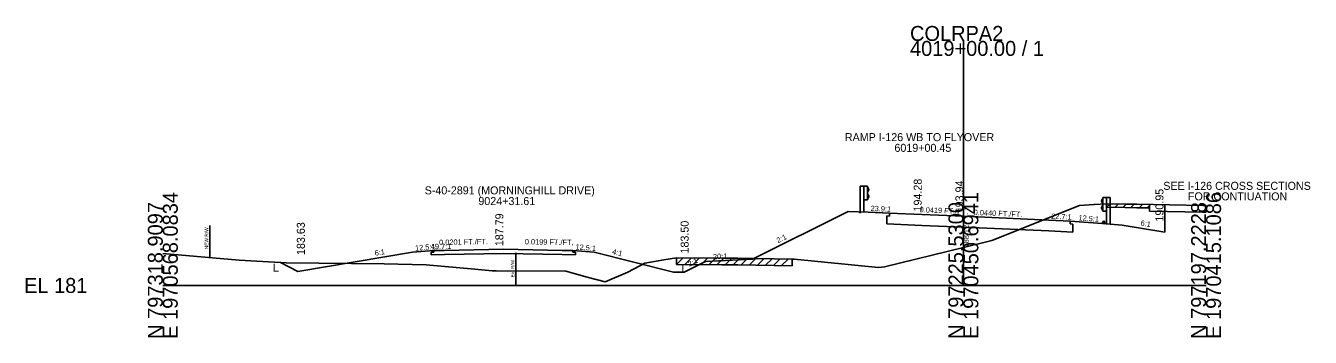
# Model space of a CAD drawing. Extents: x -26 to 1971083, y -10 to 798159.
# Drawn here: x -25.7 to 215, y 3490.3 to 3548.6 of the extents above; entities that cross this region are included whole.
import ezdxf

# ---------------------------------------------------------------- set-up
doc = ezdxf.new("R2010")
doc.units = 0
for name, color, linetype in [('RD_GPK_XS_Cell', 7, 'Continuous'), ('RD_XS_Base', 7, 'Continuous'), ('RD_XS_CurbTop', 7, 'Continuous'), ('RD_XS_EarthShd', 7, 'Continuous'), ('RD_XS_ExGround', 7, 'Continuous'), ('RD_XS_ExPaveRet', 7, 'Continuous'), ('RD_XS_ExRW', 7, 'Continuous'), ('RD_XS_GR', 7, 'Continuous'), ('RD_XS_Misc_Line', 7, 'Continuous'), ('RD_XS_NewRW', 7, 'Continuous'), ('RD_XS_Pave', 7, 'Continuous'), ('RD_XS_PaveShd', 7, 'Continuous'), ('RD_XS_TieSlope', 7, 'Continuous'), ('RD_XS_TX_Elev_EX', 7, 'Continuous'), ('RD_XS_TX_Elev_PR', 7, 'Continuous'), ('RD_XS_TX_Misc', 7, 'Continuous'), ('RD_XS_TX_MkPT', 7, 'Continuous'), ('RD_XS_TX_Notes', 7, 'Continuous'), ('RD_XS_TX_Profile', 7, 'Continuous'), ('RD_XS_TX_ShdSlope', 7, 'Continuous'), ('RD_XS_TX_Slope', 7, 'Continuous'), ('RD_XS_TX_Station', 7, 'Continuous')]:
    doc.layers.add(name, color=color, linetype=linetype)

msp = doc.modelspace()

# ---------------------------------------------------------------- linework, layer by layer
at = {"layer": 'RD_GPK_XS_Cell'}
for p, q in [((150, 3500), (150, 3545.75)), ((0, 3500), (150, 3500)), ((150, 3500), (195.47, 3500))]:
    msp.add_line(p, q, dxfattribs=at)
at = {"layer": 'RD_XS_Base'}
for p, q in [((135.67, 3513), (136.17, 3512.98)), ((135.67, 3511.52), (135.67, 3513)), ((136.17, 3512.98), (136.17, 3513.54)), ((170, 3511.5), (170, 3512.06)), ((142.19, 3511.24), (135.67, 3511.52)), ((142.19, 3511.24), (150, 3510.9)), ((150, 3510.9), (166, 3510.2)), ((166, 3510.2), (170.5, 3510)), ((170.5, 3511.48), (170, 3511.5)), ((170.5, 3510), (170.5, 3511.48)), ((50.3, 3506.22), (50.8, 3506.23)), ((50.3, 3505.74), (50.3, 3506.22)), ((52.8, 3505.79), (50.3, 3505.74)), ((50.8, 3506.23), (50.8, 3506.53)), ((52.8, 3505.79), (63.8, 3506.01)), ((63.8, 3506.01), (74.8, 3505.79)), ((74.8, 3505.79), (77.3, 3505.74)), ((76.8, 3506.23), (76.8, 3506.53)), ((77.3, 3506.22), (76.8, 3506.23)), ((77.3, 3505.74), (77.3, 3506.22))]:
    msp.add_line(p, q, dxfattribs=at)
at = {"layer": 'RD_XS_CurbTop'}
for p, q in [((176, 3511.58), (176.25, 3512.04)), ((176.47, 3511.55), (176.41, 3511.98)), ((176, 3511.58), (176.47, 3511.55))]:
    msp.add_line(p, q, dxfattribs=at)
msp.add_ellipse((176.32, 3511.96), major_axis=(0, -0.131), ratio=0.686, start_param=1.762783, end_param=4.036677, dxfattribs=at)
at = {"layer": 'RD_XS_EarthShd'}
for p, q in [((136.17, 3513.54), (132.16, 3513.7)), ((170, 3512.06), (176, 3511.58)), ((50.8, 3506.53), (46.8, 3506.21)), ((76.8, 3506.53), (80.81, 3506.21))]:
    msp.add_line(p, q, dxfattribs=at)
at = {"layer": 'RD_XS_ExGround'}
msp.add_lwpolyline([(0, 3506), (14.31, 3504.73), (23.1, 3504.26), (41.47, 3504.04), (49.34, 3503.89), (58.48, 3503.05), (61.68, 3502.76), (62.44, 3502.73), (75.48, 3502.66), (79.51, 3501.55), (82.88, 3500.65), (87.15, 3502.49), (90.31, 3504.15), (93.87, 3504.77), (96.27, 3505.16), (104.74, 3505.12), (107.73, 3505.11), (117.9, 3504.93), (118.28, 3504.89), (122.11, 3504.53), (130.29, 3503.76), (134.12, 3503.39), (135.24, 3503.48), (150, 3507.12), (155.33, 3508.43), (171.76, 3514.98), (174.5, 3515.14), (176.84, 3515.25), (180.28, 3515.2), (182.52, 3515.18), (194.83, 3514.99), (195.47, 3514.98)], dxfattribs=at)
at = {"layer": 'RD_XS_ExPaveRet'}
for p, q in [((176.84, 3514.63), (176.84, 3515.25)), ((176.84, 3514.63), (180.28, 3514.57)), ((180.28, 3514.57), (182.52, 3514.55)), ((182.52, 3514.55), (184.84, 3514.52)), ((184.84, 3515.14), (184.84, 3513.89)), ((195.47, 3514.98), (195.46, 3513.73)), ((96.27, 3503.91), (96.27, 3505.16)), ((117.9, 3504.93), (117.9, 3503.68)), ((96.27, 3503.91), (104.74, 3503.87)), ((104.74, 3503.87), (107.73, 3503.86)), ((107.73, 3503.86), (117.9, 3503.68))]:
    msp.add_line(p, q, dxfattribs=at)
msp.add_lwpolyline([(184.84, 3513.89), (194.81, 3513.74), (195.46, 3513.73)], dxfattribs=at)
at = {"layer": 'RD_XS_ExRW'}
msp.add_line((66.13, 3506.12), (66.13, 3500.12), dxfattribs=at)
at = {"layer": 'RD_XS_GR'}
for p, q in [((131.34, 3518.58), (130.67, 3518.58)), ((130.67, 3518.58), (130.67, 3513.52)), ((132.01, 3518.58), (131.34, 3518.58)), ((131.34, 3518.58), (131.34, 3513.64)), ((132.01, 3516.01), (132.01, 3518.58)), ((132.01, 3518.42), (132.28, 3517.98)), ((132.28, 3517.87), (132.01, 3517.43)), ((132.28, 3516.72), (132.01, 3517.16)), ((132.01, 3516.17), (132.28, 3516.61)), ((132.28, 3517.98), (132.28, 3517.87)), ((132.28, 3516.61), (132.28, 3516.72)), ((132.01, 3516.01), (131.34, 3516.01)), ((176.15, 3516.3), (175.88, 3515.86)), ((175.88, 3515.86), (175.88, 3515.75)), ((175.88, 3515.75), (176.15, 3515.31)), ((175.88, 3514.6), (176.15, 3515.04)), ((175.88, 3514.49), (175.88, 3514.6)), ((176.15, 3514.05), (175.88, 3514.49)), ((176.15, 3516.46), (176.81, 3516.46)), ((176.15, 3513.89), (176.15, 3516.46)), ((176.81, 3516.46), (177.48, 3516.46)), ((176.81, 3516.46), (176.81, 3511.52)), ((177.48, 3516.46), (177.48, 3511.4)), ((176.15, 3513.89), (176.81, 3513.89))]:
    msp.add_line(p, q, dxfattribs=at)
at = {"layer": 'RD_XS_Misc_Line'}
for p, q in [((176.84, 3514.63), (177.46, 3515.24)), ((178.36, 3514.6), (178.98, 3515.22)), ((179.88, 3514.58), (180.5, 3515.2)), ((181.39, 3514.56), (182.02, 3515.18)), ((182.91, 3514.54), (183.53, 3515.16)), ((184.43, 3514.52), (185.05, 3515.14)), ((96.27, 3503.91), (97.52, 3505.15)), ((97.78, 3503.9), (99.04, 3505.14)), ((99.29, 3503.89), (100.55, 3505.14)), ((100.81, 3503.89), (102.06, 3505.13)), ((102.32, 3503.88), (103.58, 3505.13)), ((103.83, 3503.88), (105.09, 3505.12)), ((105.35, 3503.87), (106.6, 3505.11)), ((106.86, 3503.86), (108.11, 3505.1)), ((108.37, 3503.85), (109.61, 3505.08)), ((109.89, 3503.82), (111.13, 3505.05)), ((111.4, 3503.79), (112.64, 3505.02)), ((112.91, 3503.77), (114.15, 3505)), ((114.43, 3503.74), (115.67, 3504.97)), ((115.94, 3503.71), (117.18, 3504.94))]:
    msp.add_line(p, q, dxfattribs=at)
at = {"layer": 'RD_XS_NewRW'}
msp.add_line((8.79, 3511.22), (8.79, 3505.22), dxfattribs=at)
at = {"layer": 'RD_XS_Pave'}
for p, q in [((142.19, 3513.28), (150, 3512.94)), ((150, 3512.94), (166, 3512.24)), ((52.8, 3506.57), (63.8, 3506.79)), ((63.8, 3506.79), (74.8, 3506.57))]:
    msp.add_line(p, q, dxfattribs=at)
at = {"layer": 'RD_XS_PaveShd'}
for p, q in [((142.19, 3513.28), (136.17, 3513.54)), ((166, 3512.24), (170, 3512.06)), ((52.8, 3506.57), (50.8, 3506.53)), ((74.8, 3506.57), (76.8, 3506.53))]:
    msp.add_line(p, q, dxfattribs=at)
at = {"layer": 'RD_XS_TieSlope'}
for p, q in [((187.75, 3509.95), (187.75, 3515.1)), ((128.39, 3513.86), (110.48, 3504.94)), ((132.16, 3513.7), (128.39, 3513.86)), ((176, 3511.58), (179.75, 3511.28)), ((179.75, 3511.28), (187.75, 3509.95)), ((46.8, 3506.21), (25.3, 3502.63)), ((80.81, 3506.21), (95.67, 3502.5)), ((101.67, 3504.5), (97.67, 3502.5)), ((101.67, 3504.5), (110.48, 3504.94)), ((25.3, 3502.63), (21.9, 3504.33)), ((95.67, 3502.5), (97.67, 3502.5))]:
    msp.add_line(p, q, dxfattribs=at)

# ---------------------------------------------------------------- texts
at = {"layer": 'RD_GPK_XS_Cell'}
for s, p in [('COLRPA2', (140, 3545.75)), ('4019+00.00 / 1', (140, 3542.95)), ('EL 181', (-26, 3498.6))]:
    msp.add_text(s, height=2.8, dxfattribs=at).set_placement(p)
for s, p in [('E 1970568.0834', (2.8, 3490)), ('E 1970450.6941', (152.8, 3490)), ('E 1970415.1086', (198.27, 3490)), ('N 797318.9097', (0, 3490)), ('N 797225.5300', (150, 3490)), ('N 797197.2228', (195.47, 3490))]:
    msp.add_text(s, height=2.8, rotation=90, dxfattribs=at).set_placement(p)
at = {"layer": 'RD_XS_ExRW'}
msp.add_text('Ex. R/W ', height=0.65, rotation=90, dxfattribs=at).set_placement((65.88, 3501.5))
at = {"layer": 'RD_XS_NewRW'}
msp.add_text('NEW R/W ', height=0.65, rotation=90, dxfattribs=at).set_placement((8.52, 3506.78))
at = {"layer": 'RD_XS_TX_Elev_EX'}
msp.add_text('188.12', height=1, rotation=90, dxfattribs=at).set_placement((151, 3507.12))
at = {"layer": 'RD_XS_TX_Elev_PR'}
for s, p in [(' 194.28', (142.19, 3513.28)), (' 193.94', (150, 3512.94)), (' 187.79', (63.8, 3506.79))]:
    msp.add_text(s, height=1.5, rotation=90, dxfattribs=at).set_placement(p)
at = {"layer": 'RD_XS_TX_Misc'}
for s, p in [('190.95', (187.48, 3511.95)), ('183.63', (26.61, 3505.7)), ('183.50', (98.52, 3505.98))]:
    msp.add_text(s, height=1.5, rotation=90, dxfattribs=at).set_placement(p)
at = {"layer": 'RD_XS_TX_MkPT'}
for p in [(20.63, 3502.6), (97.16, 3502.5)]:
    msp.add_text('L', height=1.5, dxfattribs=at).set_placement(p)
at = {"layer": 'RD_XS_TX_Notes'}
for s, p in [('SEE I-126 CROSS SECTIONS', (187.45, 3517.89)), ('FOR CONTIUATION', (192.07, 3515.92))]:
    msp.add_text(s, height=1.5, dxfattribs=at).set_placement(p)
at = {"layer": 'RD_XS_TX_Profile'}
msp.add_text('49.7:1', height=1, rotation=1.1516, dxfattribs=at).set_placement((50.22, 3506.77))
at = {"layer": 'RD_XS_TX_ShdSlope'}
for s, rotation, p in [('23.9:1', 357.6078, (132.6, 3513.94)), ('12.5:1', 355.4261, (171.54, 3512.19)), ('12.5:1', 4.573, (47.3, 3506.5)), ('12.5:1', 355.4323, (77.3, 3506.74))]:
    msp.add_text(s, height=1, rotation=rotation, dxfattribs=at).set_placement(p)
at = {"layer": 'RD_XS_TX_Slope'}
for s, rotation, p in [('0.0419 FT./FT.', 357.5987, (141.78, 3513.7)), ('0.0440 FT./FT.', 357.4806, (151.91, 3513.19)), ('22.7:1', 357.4806, (166.43, 3512.47)), ('6:1', 350.5377, (183.14, 3511.23)), ('2:1', 26.4784, (115.29, 3507.89)), ('0.0201 FT./FT.', 1.1516, (51.78, 3507.55)), ('0.0199 FT./FT.', 358.861, (67.82, 3507.71)), ('6:1', 9.4604, (39.77, 3505.55)), ('4:1', 345.971, (84.11, 3505.9)), ('2:1', 26.5651, (98.66, 3503.48)), ('20:1', 2.8624, (103.11, 3504.88))]:
    msp.add_text(s, height=1, rotation=rotation, dxfattribs=at).set_placement(p)
at = {"layer": 'RD_XS_TX_Station'}
for s, p in [('RAMP I-126 WB TO FLYOVER', (127.79, 3527)), ('6019+00.45', (137.08, 3525)), ('S-40-2891 (MORNINGHILL DRIVE)', (49.06, 3517.04)), ('9024+31.61', (59.12, 3515.04))]:
    msp.add_text(s, height=1.5, dxfattribs=at).set_placement(p)

doc.saveas('drawing.dxf')
